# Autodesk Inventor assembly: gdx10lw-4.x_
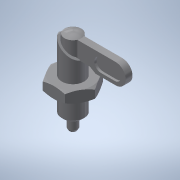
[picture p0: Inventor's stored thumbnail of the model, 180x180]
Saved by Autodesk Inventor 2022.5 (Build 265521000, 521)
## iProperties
Part Number: gdx10lw-4.x_
Material: 一般
Document SubType Name: Assembly
Designer: ImaoCorp
Sending System: SOLIDWORKS 2017-2017317
MC: AMD64
MC_MODEL: Intel64 Family 6 Model 60 Stepping 3, GenuineIntel
OS: Windows_NT
FRU: Parasolid Version 29.0, build 201,  4-17-2017
FORMAT: text
GUISE: transmit
KEY: gdx10lw-4
FILE: gdx10lw-4.x_t
DATE: Mon Jul 01 17:34:13 2019
Author: ImaoCorp
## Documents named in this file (3)
- X:\14_SW2022-Inv2022\00_全2023-1023新製品(TCC)まで\g\gdx10lw-4\GDX10LW-4.iam
- X:\14_SW2022-Inv2022\00_全2023-1023新製品(TCC)まで\g\gdx10lw-4\gdx10lw-4_01.ipt
- X:\14_SW2022-Inv2022\00_全2023-1023新製品(TCC)まで\g\gdx10lw-4\gdx10lw-4_02.ipt
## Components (2 placed, 2 different names)
1. gdx10lw-4_01
2. gdx10lw-4_02
